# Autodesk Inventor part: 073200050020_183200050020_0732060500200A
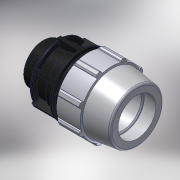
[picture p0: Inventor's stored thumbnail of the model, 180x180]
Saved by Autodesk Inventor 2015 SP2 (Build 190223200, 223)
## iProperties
Created: 2017-02
Part Number: 073200050020_183200050020_0732060500200A
Material: PVC-Piping
Description: 073200050020_183200050020_0732060500200A
Document SubType Name: Modeling
Designer: KIM
Mass: 92.6774 g
Surface Area: 199.44 cm^2
Volume: 66.1981 cm^3
Density: 1.4 g/cm^3
Appearance: PTFE
Author: Кирилл
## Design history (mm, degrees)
derived "07320.ipt"
feature "Solid1::07320.ipt"
tag "TaggingFeature1"
body "Solid1"
other parameters: "d4" = 19.71429, "d5" = 35.88, "d7" = 96, "d8" = 72, "d9" = 19.71429, "d11" = 3.94286, "d12" = 76.8, "d13" = 120 deg, "d15" = 8 deg, "d16" = 86.4, "d18" = 2.5, "d19" = 35 deg, "d20" = 17.5 deg, "d21" = 89.28, "d23" = 0, "d25" = 360 deg, "d27" = 1.92, "d34" = 4.8, "d36" = 0, "d42" = 35.88, "d43" = 2.88, "d46" = 1.5, "d49" = 109, "d51" = 138, "d53" = 1, "d55" = 360 deg, "d57" = 67, "d58" = 46.9, "d59" = 27.6, "d62" = 16, "d63" = 60.3, "d64" = 2, "E_" = 96, "H_" = 138, "l_" = 109, "L_" = 16, "B_" = 67
